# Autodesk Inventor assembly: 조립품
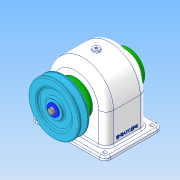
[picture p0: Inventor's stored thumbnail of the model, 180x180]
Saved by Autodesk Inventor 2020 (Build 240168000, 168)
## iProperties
Created: 2022-09
Part Number: 조립품
Document SubType Name: Assembly
Designer: user
Author: user
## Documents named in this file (16)
- C:\Users\user\Desktop\720906V1005\조립품.iam
- C:\Users\user\Desktop\720906V1005\본체.ipt
- C:\Users\user\Desktop\720906V1005\V-벨트풀리.ipt
- C:\Users\user\Desktop\720906V1005\뒤커버.ipt
- C:\Users\user\Desktop\720906V1005\멈춤나사 M4 x 10.ipt
- C:\Users\user\Desktop\720906V1005\베어링 6203.ipt
- C:\Users\user\Desktop\720906V1005\볼트 M3 x 10.ipt
- C:\Users\user\Desktop\720906V1005\스퍼기어.ipt
- C:\Users\user\Desktop\720906V1005\앞커버.ipt
- C:\Users\user\Desktop\720906V1005\오일 실 17 x 30 x 8.ipt
- C:\Users\user\Desktop\720906V1005\와셔 6 x 22.ipt
- C:\Users\user\Desktop\720906V1005\육각머리볼트 M3 x 8.ipt
- C:\Users\user\Desktop\720906V1005\축.ipt
- C:\Users\user\Desktop\720906V1005\칼라.ipt
- C:\Users\user\Desktop\720906V1005\키 5 x 5 x 18.ipt
- C:\Users\user\Desktop\720906V1005\키 6 x 6 x 22.ipt
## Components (9 placed, 2 different names)
1. V-벨트풀리:1 — 플러쉬:1
2. ISO 4762 M3 x 10:2 — 각도:4
3. ISO 4762 M3 x 10:3
4. ISO 4762 M3 x 10:4
5. ISO 4762 M3 x 10:5
6. ISO 4762 M3 x 10:6 — 각도:5
7. ISO 4762 M3 x 10:7
8. ISO 4762 M3 x 10:8
9. ISO 4762 M3 x 10:9
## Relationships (3: Angle 2, Flush 1)
- 플러쉬:1 [Flush]: V-벨트풀리:1
- 각도:4 [Angle]: ISO 4762 M3 x 10:2
- 각도:5 [Angle]: ISO 4762 M3 x 10:6
